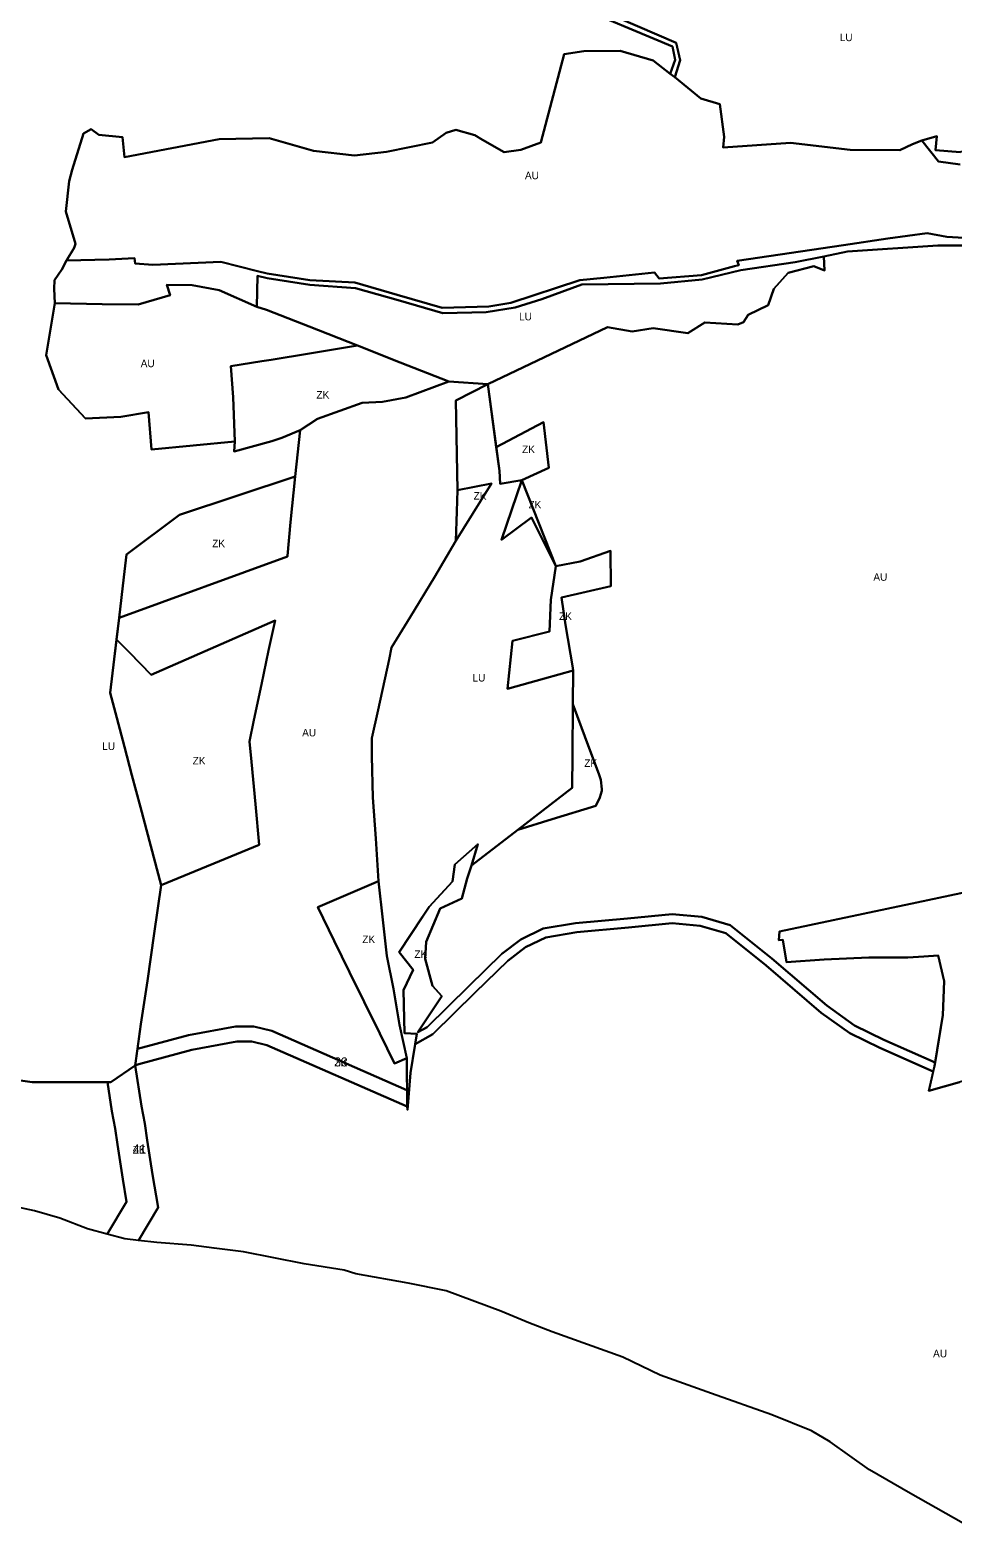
# Model space of a CAD drawing. Extents: x -521261 to -517465, y -1182764 to -1179456.
# Drawn here: x -520806 to -520192, y -1181875 to -1180873 of the extents above; entities that cross this region are included whole.
import ezdxf

# ---------------------------------------------------------------- set-up
doc = ezdxf.new("R2010")
doc.units = 0
for name, color, linetype in [('90710013', 7, 'Continuous'), ('90710023', 7, 'Continuous'), ('90750013', 7, 'Continuous'), ('90770013', 7, 'Continuous'), ('ID_navrh', 7, 'Continuous')]:
    doc.layers.add(name, color=color, linetype=linetype)

msp = doc.modelspace()

# ---------------------------------------------------------------- linework, layer by layer
at = {"layer": '90710013'}
for points in [[(-520440.58, -1180853.57), (-520376.27, -1180881.41), (-520373.63, -1180892.94), (-520377.28, -1180904.27), (-520380.19, -1180902.05), (-520376.96, -1180892.63), (-520378.72, -1180883.92), (-520447.63, -1180855.08)], [(-520187.3, -1180962.26), (-520201.71, -1180960.23), (-520212.94, -1180946.42), (-520202.96, -1180943.49), (-520203.9, -1180952.83), (-520187.42, -1180954.15)], [(-520161.81, -1181016.06), (-520202.17, -1181016.05), (-520262.27, -1181020.23), (-520278.14, -1181023.43), (-520297.08, -1181027.2), (-520333.23, -1181032.5), (-520358.9, -1181038.71), (-520386.77, -1181041.34), (-520439.04, -1181042.18), (-520465.6, -1181051.94), (-520483.49, -1181057.27), (-520502.66, -1181060.46), (-520531.56, -1181061.16), (-520561.25, -1181052.52), (-520589.61, -1181044.45), (-520619.95, -1181042.28), (-520648.35, -1181037.93), (-520654.8, -1181036.24), (-520655.3, -1181056.85), (-520680.34, -1181045.76), (-520698.14, -1181042.43), (-520715.02, -1181042.38), (-520712.92, -1181049.21), (-520734.18, -1181055.46), (-520758.188, -1181055.079), (-520789.59, -1181054.58), (-520789.95, -1181044.99), (-520789.78, -1181039.28), (-520784.95, -1181032.19), (-520781.8, -1181026.11), (-520753.55, -1181025.36), (-520736.5, -1181024.64), (-520736.16, -1181028.06), (-520724.29, -1181028.9), (-520679.07, -1181027.05), (-520654.732, -1181033.141), (-520648.3, -1181034.75), (-520619.96, -1181039.3), (-520589.94, -1181040.83), (-520561.77, -1181049.02), (-520531.99, -1181057.53), (-520500.85, -1181056.65), (-520486.21, -1181054.21), (-520440.29, -1181039.26), (-520424.35, -1181037.58), (-520390.73, -1181034.03), (-520387.65, -1181038.15), (-520359.36, -1181035.81), (-520337.45, -1181029.91), (-520334.59, -1181029.23), (-520335.73, -1181026.42), (-520264.93, -1181015.96), (-520235.48, -1181011.57), (-520209.39, -1181007.96), (-520196.24, -1181010.47), (-520140.01, -1181013.64)]]:
    msp.add_lwpolyline(points, dxfattribs=at)
for points in [[(-520527.54, -1181106.61), (-520556.17, -1181117.12), (-520571.69, -1181120.15), (-520585.05, -1181120.87), (-520614.85, -1181131.39), (-520626.5, -1181138.86), (-520638.52, -1181144.14), (-520645.15, -1181146.15), (-520670.21, -1181153.14), (-520669.91, -1181146.41), (-520670.9, -1181116.98), (-520672.52, -1181096.48), (-520652, -1181093.118), (-520645.776, -1181092.099), (-520620.095, -1181087.892), (-520588.28, -1181082.68), (-520559.83, -1181093.86)], [(-520478.96, -1181172.1), (-520493.39, -1181174.7), (-520493.92, -1181165.95), (-520496.015, -1181150.268), (-520464.56, -1181133.63), (-520460.89, -1181164.03)], [(-520746.87, -1181263.8), (-520743.69, -1181236.73), (-520741.92, -1181221.6), (-520706.63, -1181195.17), (-520629.67, -1181169.79), (-520632.77, -1181200.01), (-520634.84, -1181222.55), (-520634.86, -1181222.95)], [(-520478.96, -1181172.1), (-520456.42, -1181229.43), (-520472.47, -1181197.08), (-520492.59, -1181211.81)], [(-520506.5, -1181186.19), (-520522.96, -1181212.61), (-520522.237, -1181192.977), (-520521.72, -1181178.92), (-520499.14, -1181174.37)], [(-520456.42, -1181229.43), (-520440.2, -1181226.19), (-520420.08, -1181219.13), (-520419.8, -1181242.73), (-520452.55, -1181250.11), (-520449.84, -1181268.49), (-520445.1, -1181297.08), (-520444.74, -1181298.79), (-520463.92, -1181303.97), (-520488.58, -1181310.87), (-520485.2, -1181279.13), (-520460.48, -1181272.82), (-520459.68, -1181251.69)], [(-520656.21, -1181387.66), (-520653.67, -1181414.77), (-520718.89, -1181441.47), (-520725.79, -1181415.51), (-520732.6, -1181389.64), (-520738.26, -1181368.28), (-520743.26, -1181349.41), (-520748.34, -1181330.19), (-520752.71, -1181313.69), (-520750.08, -1181291.23), (-520748.549, -1181278.144), (-520740.001, -1181286.884), (-520725.496, -1181301.716), (-520643.12, -1181265.47), (-520647.35, -1181285.51), (-520652.13, -1181308.1), (-520657.13, -1181331.78), (-520660.11, -1181345.91), (-520658.84, -1181359.45)], [(-520425.803, -1181377.739), (-520425.72, -1181378.7), (-520427.18, -1181383.28), (-520429.63, -1181388.754), (-520458.79, -1181397.7), (-520481.69, -1181404.72), (-520460.08, -1181388.06), (-520445.56, -1181376.73), (-520445.28, -1181354.75), (-520445.05, -1181321.08), (-520434.119, -1181350.501), (-520427.824, -1181367.442), (-520426.35, -1181371.41)], [(-520538.227, -1181540.636), (-520549.888, -1181547.226), (-520548.78, -1181540.39), (-520557.03, -1181539.8), (-520557.58, -1181511.29), (-520551.17, -1181497.81), (-520560.55, -1181486.11), (-520545.05, -1181462.49), (-520540.59, -1181455.99), (-520525.16, -1181439.01), (-520523.42, -1181427.65), (-520508.13, -1181414.32), (-520512.46, -1181428.48), (-520515.29, -1181437.12), (-520518.89, -1181450.27), (-520533.273, -1181456.989), (-520542.68, -1181479.26), (-520543.3, -1181490.5), (-520538.34, -1181508.53), (-520532.26, -1181515.4), (-520548.06, -1181539.302), (-520541.872, -1181535.804), (-520514.218, -1181508.546), (-520492.239, -1181487.201), (-520479.677, -1181477.661), (-520464.745, -1181470.414), (-520443.209, -1181466.753), (-520408.656, -1181463.593), (-520378.987, -1181460.828), (-520359.314, -1181462.567), (-520340.401, -1181468.065), (-520312.596, -1181490.319), (-520276.105, -1181521.569), (-520257.724, -1181534.797), (-520238.266, -1181544.319), (-520204.075, -1181559.377), (-520204.49, -1181561.93), (-520205.27, -1181565.407), (-520240.794, -1181549.761), (-520260.816, -1181539.963), (-520279.815, -1181526.291), (-520316.424, -1181494.941), (-520343.219, -1181473.494), (-520360.426, -1181468.492), (-520378.973, -1181466.852), (-520408.104, -1181469.567), (-520442.431, -1181472.707), (-520462.895, -1181476.186), (-520476.523, -1181482.799), (-520488.32, -1181491.759), (-520510.022, -1181512.834)], [(-520555.55, -1181556.57), (-520563.757, -1181560.112), (-520573.491, -1181540.223), (-520583.812, -1181519.136), (-520593.528, -1181499.284), (-520603.731, -1181478.436), (-520614.625, -1181456.179), (-520574.24, -1181438.77), (-520571.45, -1181464.53), (-520568.81, -1181488.5), (-520564.22, -1181510.35), (-520560.33, -1181534.47)]]:
    msp.add_lwpolyline(points, close=True, dxfattribs=at)
at = {"layer": '90710023'}
for points in [[(-520645.297, -1181538.328), (-520555.405, -1181577.719), (-520555.33, -1181588.67), (-520648.488, -1181547.847), (-520658.488, -1181545.464), (-520668.488, -1181545.381), (-520698.488, -1181550.938), (-520733.75, -1181560.43), (-520736.16, -1181561.46), (-520734.645, -1181550.315), (-520700.702, -1181541.178), (-520669.365, -1181535.373), (-520657.272, -1181535.474)], [(-520720.88, -1181655.89), (-520733.876, -1181677.714), (-520742.99, -1181676.7), (-520754.671, -1181673.544), (-520741.824, -1181651.971), (-520744.352, -1181636.982), (-520747.924, -1181614.041), (-520749.513, -1181603.294), (-520751.636, -1181591.755), (-520754.655, -1181572.584), (-520752.43, -1181572.59), (-520736.16, -1181561.46), (-520731.92, -1181588.39), (-520729.78, -1181600.02), (-520728.15, -1181611.04), (-520724.61, -1181633.78)]]:
    msp.add_lwpolyline(points, close=True, dxfattribs=at)
at = {"layer": '90750013'}
for points in [[(-520140.01, -1181013.64), (-520196.24, -1181010.47), (-520209.39, -1181007.96), (-520235.48, -1181011.57), (-520264.93, -1181015.96), (-520335.73, -1181026.42), (-520334.59, -1181029.23), (-520337.45, -1181029.91), (-520359.36, -1181035.81), (-520387.65, -1181038.15), (-520390.73, -1181034.03), (-520424.35, -1181037.58), (-520440.29, -1181039.26), (-520486.21, -1181054.21), (-520500.85, -1181056.65), (-520531.99, -1181057.53), (-520561.77, -1181049.02), (-520589.94, -1181040.83), (-520619.96, -1181039.3), (-520648.3, -1181034.75), (-520654.732, -1181033.141), (-520679.07, -1181027.05), (-520724.29, -1181028.9), (-520736.16, -1181028.06), (-520736.5, -1181024.64), (-520753.55, -1181025.36), (-520781.8, -1181026.11), (-520776.76, -1181017.76), (-520775.73, -1181015.12), (-520782.22, -1180993.52), (-520780.05, -1180973.32), (-520778.12, -1180965.89), (-520770.41, -1180941.78), (-520765.33, -1180938.81), (-520760.21, -1180942.51), (-520744.49, -1180944), (-520743.19, -1180957.3), (-520680.17, -1180945.51), (-520646.99, -1180944.71), (-520617.63, -1180953.24), (-520590.31, -1180956.29), (-520569.05, -1180953.85), (-520538.35, -1180947.59), (-520529.26, -1180941.13), (-520522.77, -1180939.3), (-520510.22, -1180942.87), (-520505.09, -1180945.85), (-520490.67, -1180954.03), (-520479.73, -1180952.5), (-520466.27, -1180947.66), (-520450.85, -1180888.84), (-520437.74, -1180886.84), (-520413.63, -1180886.67), (-520391.57, -1180893.1), (-520380.19, -1180902.05), (-520377.28, -1180904.27), (-520360, -1180918.29), (-520347.18, -1180922.08), (-520344.3, -1180943.96), (-520344.99, -1180950.96), (-520300.29, -1180947.88), (-520260.64, -1180952.48), (-520227.61, -1180952.85), (-520219.04, -1180948.87), (-520212.94, -1180946.42), (-520201.71, -1180960.23), (-520187.3, -1180962.26)], [(-520147.36, -1181438.44), (-520216.32, -1181452.99), (-520307.52, -1181472.34), (-520307.98, -1181477.97), (-520305.37, -1181477.77), (-520303.01, -1181492.71), (-520277.86, -1181490.96), (-520248.06, -1181489.62), (-520222.29, -1181489.55), (-520211.67, -1181488.9), (-520201.97, -1181488.21), (-520198.13, -1181505.28), (-520198.96, -1181527.88), (-520204.075, -1181559.377), (-520238.266, -1181544.319), (-520257.724, -1181534.797), (-520276.105, -1181521.569), (-520312.596, -1181490.319), (-520340.401, -1181468.065), (-520359.314, -1181462.567), (-520378.987, -1181460.828), (-520408.656, -1181463.593), (-520443.209, -1181466.753), (-520464.745, -1181470.414), (-520479.677, -1181477.661), (-520492.239, -1181487.201), (-520514.218, -1181508.546), (-520541.872, -1181535.804), (-520548.06, -1181539.302), (-520532.26, -1181515.4), (-520538.34, -1181508.53), (-520543.3, -1181490.5), (-520542.68, -1181479.26), (-520533.273, -1181456.989), (-520518.89, -1181450.27), (-520515.29, -1181437.12), (-520512.46, -1181428.48), (-520481.69, -1181404.72), (-520458.79, -1181397.7), (-520429.63, -1181388.754), (-520427.18, -1181383.28), (-520425.72, -1181378.7), (-520425.803, -1181377.739), (-520426.35, -1181371.41), (-520427.824, -1181367.442), (-520434.119, -1181350.501), (-520445.05, -1181321.08), (-520444.74, -1181298.79), (-520445.1, -1181297.08), (-520449.84, -1181268.49), (-520452.55, -1181250.11), (-520419.8, -1181242.73), (-520420.08, -1181219.13), (-520440.2, -1181226.19), (-520456.42, -1181229.43), (-520478.96, -1181172.1), (-520460.89, -1181164.03), (-520464.56, -1181133.63), (-520496.015, -1181150.268), (-520501.61, -1181108.38), (-520422.02, -1181070.48), (-520405.61, -1181073.38), (-520391.51, -1181071.12), (-520368.56, -1181074.46), (-520357.23, -1181067.33), (-520335.2, -1181068.61), (-520331.46, -1181067.2), (-520328.37, -1181062.33), (-520315.05, -1181055.77), (-520311.25, -1181044.99), (-520301.71, -1181034.37), (-520284.69, -1181029.91), (-520277.6, -1181032.76), (-520278.14, -1181023.43), (-520262.27, -1181020.23), (-520202.17, -1181016.05), (-520161.81, -1181016.06)], [(-520168.26, -1181875.49), (-520220.41, -1181846.07), (-520247.74, -1181830.3), (-520273.94, -1181811.64), (-520286.37, -1181804.39), (-520312.77, -1181793.79), (-520352.8, -1181779.41), (-520386.86, -1181767.21), (-520411.78, -1181755.41), (-520458.77, -1181738.57), (-520474.31, -1181732.61), (-520492.99, -1181724.81), (-520529.33, -1181711.19), (-520554.52, -1181706.12), (-520589.48, -1181699.97), (-520597.15, -1181697.6), (-520623.84, -1181693.35), (-520664.1, -1181685.3), (-520683.63, -1181682.77), (-520698.99, -1181680.78), (-520721.77, -1181679.06), (-520733.876, -1181677.714), (-520720.88, -1181655.89), (-520724.61, -1181633.78), (-520728.15, -1181611.04), (-520729.78, -1181600.02), (-520731.92, -1181588.39), (-520736.16, -1181561.46), (-520733.75, -1181560.43), (-520698.488, -1181550.938), (-520668.488, -1181545.381), (-520658.488, -1181545.464), (-520648.488, -1181547.847), (-520555.33, -1181588.67), (-520554.96, -1181590.89), (-520552.96, -1181566.19), (-520549.888, -1181547.226), (-520538.227, -1181540.636), (-520510.022, -1181512.834), (-520488.32, -1181491.759), (-520476.523, -1181482.799), (-520462.895, -1181476.186), (-520442.431, -1181472.707), (-520408.104, -1181469.567), (-520378.973, -1181466.852), (-520360.426, -1181468.492), (-520343.219, -1181473.494), (-520316.424, -1181494.941), (-520279.815, -1181526.291), (-520260.816, -1181539.963), (-520240.794, -1181549.761), (-520205.27, -1181565.407), (-520208.16, -1181578.29), (-520187.89, -1181572.452)], [(-520832.67, -1181568.56), (-520804.67, -1181572.45), (-520754.655, -1181572.584), (-520751.636, -1181591.755), (-520749.513, -1181603.294), (-520747.924, -1181614.041), (-520744.352, -1181636.982), (-520741.824, -1181651.971), (-520754.671, -1181673.544), (-520767.86, -1181669.98), (-520786.31, -1181662.97), (-520803.11, -1181658.11), (-520817.41, -1181654.92)]]:
    msp.add_lwpolyline(points, dxfattribs=at)
for points in [[(-520588.28, -1181082.68), (-520620.095, -1181087.892), (-520645.776, -1181092.099), (-520652, -1181093.118), (-520672.52, -1181096.48), (-520670.9, -1181116.98), (-520669.91, -1181146.41), (-520725.36, -1181151.77), (-520727.31, -1181126.94), (-520745.59, -1181130), (-520769.1, -1181131.19), (-520787.16, -1181111.94), (-520795.31, -1181089.15), (-520789.59, -1181054.58), (-520758.188, -1181055.079), (-520734.18, -1181055.46), (-520712.92, -1181049.21), (-520715.02, -1181042.38), (-520698.14, -1181042.43), (-520680.34, -1181045.76), (-520655.3, -1181056.85), (-520648.69, -1181058.96), (-520620.31, -1181070.08)], [(-520501.61, -1181108.38), (-520522.92, -1181119.2), (-520521.72, -1181178.92), (-520522.237, -1181192.977), (-520522.96, -1181212.61), (-520537.12, -1181236.65), (-520553.33, -1181263.31), (-520565.67, -1181283.42), (-520567.22, -1181291.34), (-520574.59, -1181324.96), (-520578.82, -1181343.7), (-520578.73, -1181355.74), (-520577.99, -1181383.26), (-520576.08, -1181410.39), (-520574.24, -1181438.77), (-520614.625, -1181456.179), (-520603.731, -1181478.436), (-520593.528, -1181499.284), (-520583.812, -1181519.136), (-520573.491, -1181540.223), (-520563.757, -1181560.112), (-520555.55, -1181556.57), (-520555.405, -1181577.719), (-520645.297, -1181538.328), (-520657.272, -1181535.474), (-520669.365, -1181535.373), (-520700.702, -1181541.178), (-520734.645, -1181550.315), (-520732.41, -1181533.87), (-520728.04, -1181505.07), (-520723.52, -1181473.69), (-520718.89, -1181441.47), (-520653.67, -1181414.77), (-520656.21, -1181387.66), (-520658.84, -1181359.45), (-520660.11, -1181345.91), (-520657.13, -1181331.78), (-520652.13, -1181308.1), (-520647.35, -1181285.51), (-520643.12, -1181265.47), (-520725.496, -1181301.716), (-520740.001, -1181286.884), (-520748.549, -1181278.144), (-520746.87, -1181263.8), (-520634.86, -1181222.95), (-520634.84, -1181222.55), (-520632.77, -1181200.01), (-520629.67, -1181169.79), (-520626.5, -1181138.86), (-520614.85, -1181131.39), (-520585.05, -1181120.87), (-520571.69, -1181120.15), (-520556.17, -1181117.12), (-520527.54, -1181106.61)]]:
    msp.add_lwpolyline(points, close=True, dxfattribs=at)
at = {"layer": '90770013'}
for points in [[(-520203.9, -1180952.83), (-520202.96, -1180943.49), (-520212.94, -1180946.42), (-520219.04, -1180948.87), (-520227.61, -1180952.85), (-520260.64, -1180952.48), (-520300.29, -1180947.88), (-520344.99, -1180950.96), (-520344.3, -1180943.96), (-520347.18, -1180922.08), (-520360, -1180918.29), (-520377.28, -1180904.27), (-520373.63, -1180892.94), (-520376.27, -1180881.41), (-520440.58, -1180853.57), (-520296.21, -1180829.93), (-520153.4, -1180806.35), (-520157.92, -1180932.93), (-520165.05, -1180947.64), (-520187.42, -1180954.15)], [(-520501.61, -1181108.38), (-520527.54, -1181106.61), (-520559.83, -1181093.86), (-520588.28, -1181082.68), (-520620.31, -1181070.08), (-520648.69, -1181058.96), (-520655.3, -1181056.85), (-520654.8, -1181036.24), (-520648.35, -1181037.93), (-520619.95, -1181042.28), (-520589.61, -1181044.45), (-520561.25, -1181052.52), (-520531.56, -1181061.16), (-520502.66, -1181060.46), (-520483.49, -1181057.27), (-520465.6, -1181051.94), (-520439.04, -1181042.18), (-520386.77, -1181041.34), (-520358.9, -1181038.71), (-520333.23, -1181032.5), (-520297.08, -1181027.2), (-520278.14, -1181023.43), (-520277.6, -1181032.76), (-520284.69, -1181029.91), (-520301.71, -1181034.37), (-520311.25, -1181044.99), (-520315.05, -1181055.77), (-520328.37, -1181062.33), (-520331.46, -1181067.2), (-520335.2, -1181068.61), (-520357.23, -1181067.33), (-520368.56, -1181074.46), (-520391.51, -1181071.12), (-520405.61, -1181073.38), (-520422.02, -1181070.48)], [(-520501.61, -1181108.38), (-520493.92, -1181165.95), (-520493.39, -1181174.7), (-520478.96, -1181172.1), (-520492.59, -1181211.81), (-520472.47, -1181197.08), (-520456.42, -1181229.43), (-520459.68, -1181251.69), (-520460.48, -1181272.82), (-520485.2, -1181279.13), (-520488.58, -1181310.87), (-520463.92, -1181303.97), (-520444.74, -1181298.79), (-520445.05, -1181321.08), (-520445.28, -1181354.75), (-520445.56, -1181376.73), (-520460.08, -1181388.06), (-520481.69, -1181404.72), (-520512.46, -1181428.48), (-520508.13, -1181414.32), (-520523.42, -1181427.65), (-520525.16, -1181439.01), (-520540.59, -1181455.99), (-520545.05, -1181462.49), (-520560.55, -1181486.11), (-520551.17, -1181497.81), (-520557.58, -1181511.29), (-520557.03, -1181539.8), (-520548.78, -1181540.39), (-520552.96, -1181566.19), (-520554.96, -1181590.89), (-520555.33, -1181588.67), (-520555.55, -1181556.57), (-520560.33, -1181534.47), (-520564.22, -1181510.35), (-520568.81, -1181488.5), (-520571.45, -1181464.53), (-520574.24, -1181438.77), (-520576.08, -1181410.39), (-520577.99, -1181383.26), (-520578.73, -1181355.74), (-520578.82, -1181343.7), (-520574.59, -1181324.96), (-520567.22, -1181291.34), (-520565.67, -1181283.42), (-520553.33, -1181263.31), (-520537.12, -1181236.65), (-520522.96, -1181212.61), (-520506.5, -1181186.19), (-520499.14, -1181174.37), (-520521.72, -1181178.92), (-520522.92, -1181119.2)]]:
    msp.add_lwpolyline(points, close=True, dxfattribs=at)
for points in [[(-520447.63, -1180855.08), (-520378.72, -1180883.92), (-520376.96, -1180892.63), (-520380.19, -1180902.05), (-520391.57, -1180893.1), (-520413.63, -1180886.67), (-520437.74, -1180886.84), (-520450.85, -1180888.84), (-520466.27, -1180947.66), (-520479.73, -1180952.5), (-520490.67, -1180954.03), (-520505.09, -1180945.85), (-520510.22, -1180942.87), (-520522.77, -1180939.3), (-520529.26, -1180941.13), (-520538.35, -1180947.59), (-520569.05, -1180953.85), (-520590.31, -1180956.29), (-520617.63, -1180953.24), (-520646.99, -1180944.71), (-520680.17, -1180945.51), (-520743.19, -1180957.3), (-520744.49, -1180944), (-520760.21, -1180942.51), (-520765.33, -1180938.81), (-520770.41, -1180941.78), (-520778.12, -1180965.89), (-520780.05, -1180973.32), (-520782.22, -1180993.52), (-520775.73, -1181015.12), (-520776.76, -1181017.76), (-520781.8, -1181026.11), (-520784.95, -1181032.19), (-520789.78, -1181039.28), (-520789.95, -1181044.99), (-520789.59, -1181054.58), (-520795.31, -1181089.15), (-520787.16, -1181111.94), (-520769.1, -1181131.19), (-520745.59, -1181130), (-520727.31, -1181126.94), (-520725.36, -1181151.77), (-520669.91, -1181146.41), (-520670.21, -1181153.14), (-520645.15, -1181146.15), (-520638.52, -1181144.14), (-520626.5, -1181138.86), (-520629.67, -1181169.79), (-520706.63, -1181195.17), (-520741.92, -1181221.6), (-520743.69, -1181236.73), (-520746.87, -1181263.8), (-520750.08, -1181291.23), (-520752.71, -1181313.69), (-520748.34, -1181330.19), (-520743.26, -1181349.41), (-520738.26, -1181368.28), (-520732.6, -1181389.64), (-520725.79, -1181415.51), (-520718.89, -1181441.47), (-520723.52, -1181473.69), (-520728.04, -1181505.07), (-520732.41, -1181533.87), (-520736.16, -1181561.46), (-520752.43, -1181572.59), (-520804.67, -1181572.45), (-520832.67, -1181568.56)], [(-520174.55, -1181568.61), (-520208.16, -1181578.29), (-520204.49, -1181561.93), (-520198.96, -1181527.88), (-520198.13, -1181505.28), (-520201.97, -1181488.21), (-520211.67, -1181488.9), (-520222.29, -1181489.55), (-520248.06, -1181489.62), (-520277.86, -1181490.96), (-520303.01, -1181492.71), (-520305.37, -1181477.77), (-520307.98, -1181477.97), (-520307.52, -1181472.34), (-520216.32, -1181452.99), (-520147.36, -1181438.44)]]:
    msp.add_lwpolyline(points, dxfattribs=at)

# ---------------------------------------------------------------- texts
at = {"layer": '90710013'}
for rotation, p in [(360, (-520615.543, -1181117.91)), (0, (-520478.788, -1181154.165)), (0, (-520511.05, -1181185.132)), (0, (-520474.505, -1181191.001)), (0, (-520684.908, -1181216.795)), (0, (-520454.19, -1181265.163)), (360, (-520697.915, -1181361.232)), (360, (-520437.448, -1181362.9)), (360, (-520585.087, -1181479.988)), (360, (-520550.403, -1181489.864))]:
    msp.add_text('ZK', height=5, rotation=rotation, dxfattribs=at).set_placement(p)
at = {"layer": '90710023'}
for rotation, p in [(360, (-520603.685, -1181562.022)), (0, (-520737.776, -1181619.923))]:
    msp.add_text('ZK', height=5, rotation=rotation, dxfattribs=at).set_placement(p)
at = {"layer": '90750013'}
for rotation, p in [(0, (-520476.888, -1180972.1)), (360, (-520732.474, -1181097.075)), (360, (-520245.15, -1181239.073)), (360, (-520625.079, -1181342.568)), (0, (-520205.412, -1181755.447))]:
    msp.add_text('AU', height=5, rotation=rotation, dxfattribs=at).set_placement(p)
at = {"layer": '90770013'}
for rotation, p in [(360, (-520267.494, -1180880.25)), (0, (-520480.802, -1181065.905)), (360, (-520511.78, -1181306.084)), (360, (-520758.07, -1181351.603))]:
    msp.add_text('LU', height=5, rotation=rotation, dxfattribs=at).set_placement(p)
at = {"layer": 'ID_navrh'}
for s, rotation, p in [('33', 360, (-520603.685, -1181562.022)), ('41', 0, (-520737.776, -1181619.923))]:
    msp.add_text(s, height=6, rotation=rotation, dxfattribs=at).set_placement(p)

doc.saveas('drawing.dxf')
